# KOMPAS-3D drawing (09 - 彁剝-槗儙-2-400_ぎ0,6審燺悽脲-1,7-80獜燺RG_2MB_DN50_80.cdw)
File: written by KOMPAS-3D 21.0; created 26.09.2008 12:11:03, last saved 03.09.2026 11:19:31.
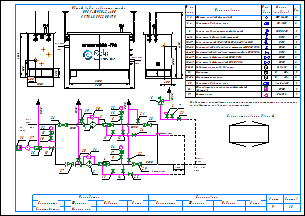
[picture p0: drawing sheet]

Sheets 1-2: A3, landscape

Document properties: Наименование: Макро:21; Автор: RaskoAdmin; Форматы листов документа: 2xA3; Полное имя файла: \\UR38nt01\Departments\КТО\КБ ПУРДГ\Заявки\Прайс-лист на типовые шкафы ГРПШ\ПРДГ_стандарт_20_03_2026\ПРДГ с RG_2MB\ПРДГ-ШУГО-2-400_до0,6МПа_Рвых-1,7-80кПа_RG_2MB_DN50_80.cdw

Title block, sheet 1: Наименование: Пункт учета газа / ПУГ-Ш-400-Р / ЛГТИ.485922.001ТУ; designation: ЛГТИ.03.4411141; sheet number: 1; Количество листов документа: 2; organisation: ООО "ЭЛЬСТЕР Газэлектроника"; Форматы листов документа: A3; stored path: C:\Рабочие документы\Компас\ПУГ\Схема.cdw; Разработал: Устинов; Проверил: Кошкин; Утвердил: Кошкин
Title block, sheet 2: sheet number: 2; stored path: D:\Рабочие документы\Заявки\ПУРДГ\ПУРДГ-ШУЭО-2-100-Р 4411220.cdw; designation, second copy: ЛГТИ.03.4411141-

Views: Вид 1, Вид 2
Referenced files: wcvoit.frw
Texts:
  Normal
  Вход
  газа
  PDI
  Выход
  Р=     кПа
  DN80
  DN50
  DN20
  Импульс DN20
  ≥5DN
  HYSWLongFangSong
  Общий вид и габариты шкафа
  ПРДГ-ШУГО-2-400
  Выход газа
  Вход газа
  Р=        МПа
  logo-rasko-ge.png
  № на
  схеме
  Усл.
  обозн.
  Марка
  (модель)
  Кол.
  Фильтр газовый фланцевый
  ФГ 16-50
  Регулятор давления газа
  RG/2MB
  Клапан предохранительный сбросной
  КПС DN20
  Кран шаровой газовый латунный
  DN15
  Кран кнопочный VE-РАСКО-НЗ-1,6-G1/2-М20
  Кран шаровой "под приварку" штуцерный DN20 PN16
  Кран шаровой "под приварку" штуцерный п/п DN15 PN16
  Кран шаровой фланцевый DN50 PN16
  Кран шаровой фланцевый DN80 PN16
  Индикатор перепада давления
  Delta 15
  Манометр
  Манометр-напоромер
  0...     МПа
  0...     кПа
  Обогреватель газогорелочный шкафной
  (Эльтон")
  Счетчик газа
  Venio-A-15
  ОГШН
  BK-G1,6
  Схема открывания дверей
  Предприятие изготовитель может заменять комплектующие на аналогичные,
  не ухудшающие заявленных характеристик.
  Должность
  Конструктор
  Фамилия
  Подпись
  Дата
  Согласовано
  Максимкин
  Лист
  Листов
  POLYLINE_STYLE_0.18_RGB_0_0_0
  POLYLINE_STYLE_0.50_RGB_0_0_0
  POLYLINE_STYLE_0.34_RGB_0_0_0
  PHANTOM_RGB_0_0_0_SC_1_THICK_0.18
  K5LT_THIN_RGB_0_0_0_THICK_0.18
  K5LT32769_RGB_0_0_0_THICK_0.18
  K5LT12_RGB_0_0_0_SC_1_THICK_0.18
  K5LT_DASHED_RGB_0_0_0_SC_1_THICK_0.18
  ACISOTGL_RGB_0_0_0_SC_0.8_THICK_0.25
  CONTINUOUS_RGB_0_127_31_THICK_0.3
  CONTINUOUS_RGB_0_0_255_THICK_0.35
  CONTINUOUS_RGB_255_0_0_THICK_0.35
  POLYLINE_STYLE_0.25_RGB_0_0_0
  CONTINUOUS_RGB_0_0_0_THICK_0.5
  POLYLINE_STYLE_0.35_RGB_0_0_255
  CONTINUOUS_RGB_0_0_0_THICK_0.4
  CONTINUOUS_RGB_0_0_0_THICK_0.35
  Без оформления
Dimensions and other numbers on the sheet: 1; 2; 3; 4; 5; 10; 27; 28; 29; 23; 8; 12; 19; 20; 21; 22; 25; 24; 30; 31; 15; 16; 26; 6; 7; 11; 14; 13; 33; 400; 1050; 500; 305; 2300; 1565; 32; 2600; 9; 17; 34; 1000; 4130; 1, 2; 3, 4; 6-14; 15-17; 18-23; 24-25; 26-27; 28-29; 30-31; 33-34; 35; 36; 37; 18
